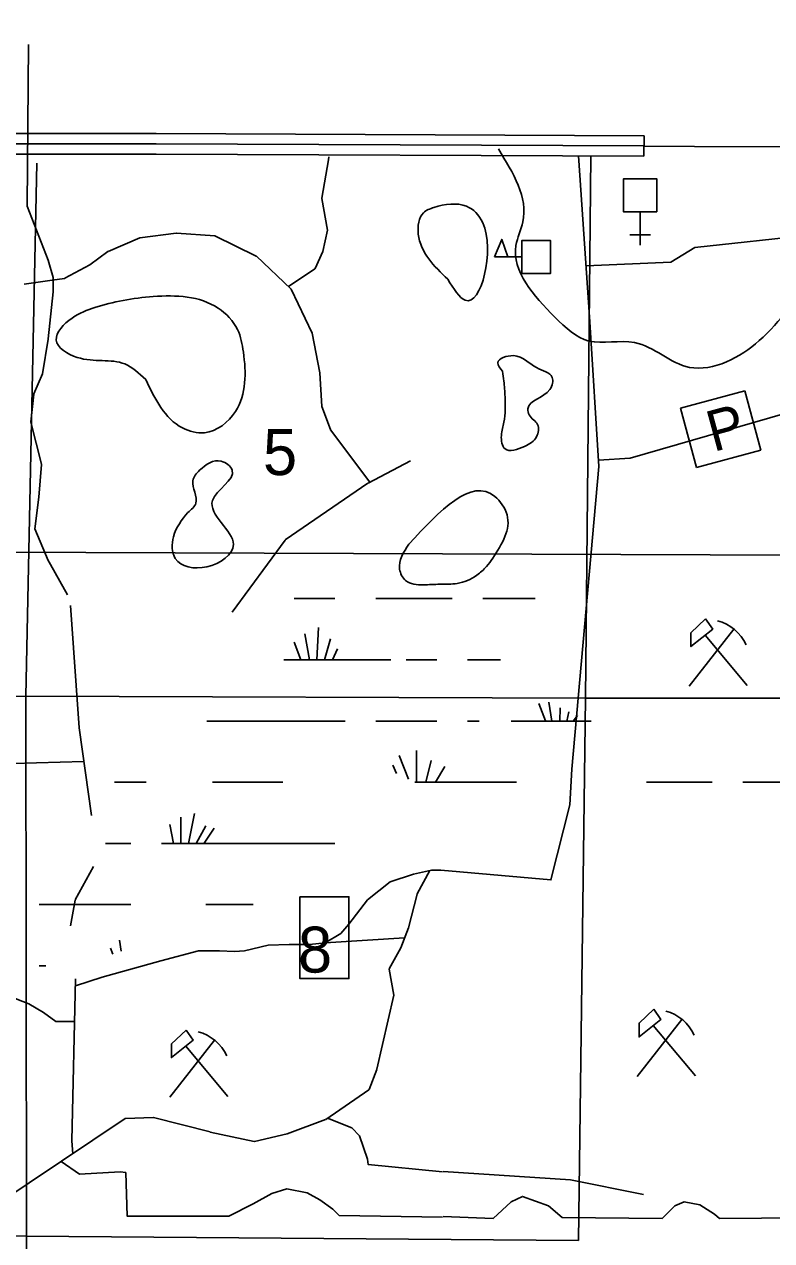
# Model space of a CAD drawing. Extents: x 408847 to 817539, y 923858 to 1151780.
# Drawn here: x 515560 to 522887, y 1099109 to 1111033 of the extents above; entities that cross this region are included whole.
import ezdxf

# ---------------------------------------------------------------- set-up
doc = ezdxf.new("R2010")
doc.units = 0
for name, color, linetype in [('County Route Divided Highway Outline and Fill', 7, 'Continuous'), ('County Routes Highway Center Lines', 7, 'Continuous'), ('Culture', 7, 'Continuous'), ('Lakes and Ponds', 7, 'Continuous'), ('Level 43', 7, 'Continuous'), ('Level 8', 7, 'Continuous'), ('Local Roads Paved', 7, 'Continuous'), ('Local Roads Related Cells', 7, 'Continuous'), ('Local Roads Related Text', 7, 'Continuous'), ('Masks for Text', 7, 'Continuous'), ('Narrow River Creek and Branch and Slough', 7, 'Continuous'), ('Quad Borders', 7, 'Continuous'), ('Section Lines', 7, 'Continuous'), ('Swamps', 7, 'Continuous')]:
    doc.layers.add(name, color=color, linetype=linetype)

msp = doc.modelspace()

# ---------------------------------------------------------------- linework, layer by layer
at = {"layer": 'County Route Divided Highway Outline and Fill'}
msp.add_lwpolyline([(483770, 1110858), (485025, 1110791), (485695, 1110804), (487095, 1110924), (487695, 1110924), (492040, 1110851), (493388, 1110671), (493666, 1110671), (497184, 1110665), (504437, 1110658), (507039, 1110658), (507716, 1110731), (508655, 1110731), (512766, 1110664), (514564, 1109861), (516852, 1109861), (521636, 1109841)], dxfattribs=at)
at = {"layer": 'County Routes Highway Center Lines'}
msp.add_lwpolyline([(526987, 1109832), (522131, 1109834), (521639, 1109839)], dxfattribs=at)
at = {"layer": 'Culture'}
for p, q in [((521599, 1109194), (521599, 1108868)), ((521699, 1108969), (521498, 1108969)), ((520438, 1108752), (520302, 1108752)), ((522078, 1104543), (522515, 1105103)), ((522234, 1105044), (522647, 1104551)), ((521570, 1100717), (522007, 1101276)), ((521727, 1101218), (522140, 1100725)), ((516985, 1100514), (517423, 1101073)), ((517142, 1101015), (517555, 1100522))]:
    msp.add_line(p, q, dxfattribs=at)
for points in [[(521761, 1109194), (521436, 1109194), (521436, 1109519), (521761, 1109519)], [(520170, 1108752), (520241, 1108924), (520302, 1108752)], [(520438, 1108589), (520438, 1108914), (520718, 1108914), (520718, 1108589)], [(522240, 1105204), (522310, 1105104), (522095, 1104932), (522095, 1105067)], [(521733, 1101377), (521802, 1101278), (521587, 1101106), (521587, 1101241)], [(517148, 1101174), (517217, 1101075), (517002, 1100903), (517002, 1101038)]]:
    msp.add_lwpolyline(points, close=True, dxfattribs=at)
for centre in [(522244, 1104770), (521736, 1100944), (517152, 1100741)]:
    msp.add_arc(centre, 431, 24.5415, 74.8304, dxfattribs=at)
at = {"layer": 'Lakes and Ponds'}
msp.add_line((520154, 1105798), (520154, 1105798), dxfattribs=at)
for points in [[(519711, 1108534), (519882, 1108327), (520054, 1109088), (519895, 1109249), (519576, 1109237), (519474, 1109186), (519423, 1108977), (519711, 1108534)], [(516750, 1107550), (517111, 1107076), (517327, 1107029), (517630, 1107237), (517708, 1107819), (517650, 1108040), (517460, 1108251), (516824, 1108364), (516251, 1108256), (516028, 1108153), (515873, 1107937), (516078, 1107768), (516544, 1107703), (516750, 1107550)], [(520249, 1107631), (520261, 1107536), (520273, 1107382), (520261, 1107133), (520237, 1107002), (520273, 1106871), (520463, 1106895), (520582, 1106990), (520593, 1107109), (520510, 1107204), (520498, 1107263), (520712, 1107453), (520736, 1107572), (520582, 1107667), (520356, 1107785), (520202, 1107714), (520249, 1107631)], [(517163, 1106248), (517022, 1106010), (517040, 1105797), (517350, 1105715), (517610, 1105932), (517404, 1106365), (517598, 1106663), (517490, 1106751), (517279, 1106661), (517212, 1106558), (517242, 1106337), (517163, 1106248)], [(519330, 1105938), (520174, 1106404), (520293, 1106224), (520154, 1105798)], [(520154, 1105798), (520090, 1105718), (519996, 1105632), (519804, 1105552), (519636, 1105544), (519470, 1105538), (519298, 1105580), (519240, 1105692), (519330, 1105938)]]:
    msp.add_spline(points, degree=3, dxfattribs=at)
at = {"layer": 'Level 8'}
msp.add_line((521636, 1109941), (521635, 1109741), dxfattribs=at)
for points in [[(482448, 1111033), (485026, 1110891), (485690, 1110904), (487091, 1111024), (487696, 1111024), (492048, 1110951), (493394, 1110771), (493666, 1110771), (497184, 1110765), (504437, 1110758), (507034, 1110758), (507711, 1110831), (508655, 1110831), (512788, 1110764), (514586, 1109961), (516852, 1109961), (521636, 1109941)], [(521635, 1109741), (516851, 1109761), (514543, 1109761), (512744, 1110565), (508654, 1110631), (507721, 1110631), (507044, 1110558), (504437, 1110558), (497184, 1110565), (493666, 1110571), (493381, 1110571), (492033, 1110751), (487695, 1110824), (487100, 1110824), (485700, 1110705), (485023, 1110691), (482448, 1110831)]]:
    msp.add_lwpolyline(points, dxfattribs=at)
at = {"layer": 'Local Roads Paved'}
for p, q in [((515587, 1109252), (515602, 1110836)), ((518543, 1109704), (518477, 1109327)), ((518545, 1109735), (518543, 1109705)), ((518477, 1109326), (518533, 1109016)), ((515795, 1108722), (515588, 1109250)), ((516692, 1108939), (516381, 1108807)), ((517050, 1108986), (516693, 1108939)), ((517428, 1108958), (517051, 1108986)), ((517834, 1108760), (517429, 1108958)), ((518533, 1109014), (518486, 1108807)), ((516380, 1108807), (516201, 1108675)), ((518486, 1108807), (518411, 1108638)), ((515842, 1108552), (515795, 1108722)), ((518174, 1108439), (517835, 1108759)), ((516201, 1108675), (515956, 1108543)), ((518409, 1108636), (518151, 1108461)), ((515833, 1108524), (515560, 1108486)), ((515955, 1108542), (515833, 1108524)), ((515842, 1108410), (515842, 1108551)), ((518382, 1108005), (518175, 1108438)), ((515795, 1107948), (515842, 1108410)), ((518458, 1107617), (518382, 1108004)), ((515739, 1107608), (515795, 1107947)), ((515654, 1107410), (515738, 1107607)), ((518476, 1107287), (518458, 1107617)), ((515625, 1107136), (515654, 1107408)), ((518561, 1107060), (518477, 1107286)), ((515729, 1106720), (515625, 1107134)), ((518948, 1106544), (518562, 1107059)), ((515701, 1106398), (515729, 1106719)), ((518930, 1106535), (519345, 1106752)), ((518118, 1105978), (518929, 1106534)), ((515663, 1106088), (515701, 1106398)), ((515795, 1105775), (515663, 1106086)), ((517598, 1105269), (518117, 1105977)), ((515786, 1105788), (515984, 1105439)), ((516012, 1105335), (516097, 1104135)), ((516097, 1104135), (516220, 1103276)), ((516145, 1103805), (515446, 1103786)), ((516239, 1102778), (516060, 1102449)), ((519411, 1102508), (519537, 1102738)), ((519326, 1102177), (519411, 1102507)), ((516059, 1102448), (516012, 1102194)), ((519251, 1101979), (519326, 1102177)), ((518510, 1102028), (519288, 1102078)), ((519138, 1101772), (519250, 1101978)), ((519184, 1101517), (519138, 1101769)), ((519015, 1100789), (519184, 1101515)), ((518940, 1100591), (519015, 1100788)), ((518515, 1100298), (518938, 1100589)), ((515211, 1099410), (516550, 1100306)), ((516552, 1100307), (516824, 1100316)), ((516825, 1100316), (517381, 1100175)), ((518137, 1100156), (518514, 1100297)), ((517381, 1100174), (517815, 1100080)), ((517816, 1100080), (518136, 1100156))]:
    msp.add_line(p, q, dxfattribs=at)
for points in [[(519645, 1102742), (520723, 1102645), (520907, 1103382), (520928, 1103730), (521194, 1106697), (521106, 1108115), (520994, 1109745)], [(524512, 1109031), (523771, 1108825), (523668, 1108825), (523280, 1108968), (522134, 1108845), (521900, 1108700), (521068, 1108664)], [(524517, 1106780), (524118, 1106718), (524036, 1107209), (523480, 1107350), (521500, 1106779), (521190, 1106761)], [(516062, 1101608), (516324, 1101691), (516899, 1101852), (517267, 1101951), (517474, 1101951), (517620, 1101944), (517720, 1101951), (517950, 1102005), (518157, 1102013), (518356, 1102013), (518510, 1102028), (518663, 1102120), (518740, 1102212), (518924, 1102450), (519146, 1102627), (519376, 1102703), (519553, 1102742), (519645, 1102742)], [(516063, 1101675), (516025, 1100087), (516035, 1099961)], [(516053, 1101258), (515869, 1101258), (515749, 1101345), (515603, 1101430), (515411, 1101506), (515212, 1101506), (515051, 1101499), (514844, 1101430), (514644, 1101414), (514437, 1101445), (514338, 1101491), (514223, 1101491), (513946, 1101529), (513762, 1101568), (513617, 1101583), (513486, 1101529), (513371, 1101506), (513157, 1101529), (513103, 1101560)], [(518531, 1100309), (518771, 1100215), (518847, 1100138), (518924, 1099908), (518932, 1099854), (519660, 1099785)], [(515921, 1099885), (516102, 1099762), (516500, 1099785), (516554, 1099777), (516569, 1099348), (517566, 1099348), (517804, 1099471), (517988, 1099570), (518134, 1099616), (518333, 1099578), (518456, 1099509), (518586, 1099417), (518648, 1099355), (519660, 1099340)], [(519667, 1099787), (520914, 1099705), (521630, 1099562)], [(519667, 1099347), (520158, 1099327), (520332, 1099490), (520444, 1099542), (520700, 1099450), (520833, 1099337), (521814, 1099327), (521937, 1099450), (522029, 1099490), (522182, 1099460), (522326, 1099368), (522377, 1099327), (523614, 1099337), (523860, 1099593), (524003, 1099675), (524146, 1099675), (524309, 1099531), (524442, 1099337), (525629, 1099306), (525925, 1099163), (527203, 1099153), (527173, 1099460)]]:
    msp.add_lwpolyline(points, dxfattribs=at)
for centre, start, end in [((518539, 1109705), 350.0787, 355.2425), ((518481, 1109327), 170.0786, 190.2998), ((515591, 1109252), 179.4701, 201.4379), ((516693, 1108935), 97.4996, 112.9991), ((517051, 1108982), 85.7087, 97.4996), ((517427, 1108954), 63.959, 85.7087), ((518529, 1109015), 347.202, 10.2998), ((516383, 1108803), 112.9991, 126.3981), ((518482, 1108808), 336.0482, 347.202), ((515791, 1108721), 15.5167, 21.4379), ((517832, 1108756), 46.6222, 63.959), ((516199, 1108678), 298.3128, 306.3981), ((518407, 1108640), 304.1731, 336.0482), ((515832, 1108528), 277.8572, 278.7505), ((515838, 1108551), 0, 15.5167), ((515954, 1108546), 278.7505, 298.3128), ((518171, 1108436), 25.5487, 46.6222), ((515838, 1108410), 354.1766, 0), ((518378, 1108003), 11.0355, 25.5487), ((515791, 1107948), 350.5424, 354.1766), ((515735, 1107608), 336.8118, 350.5424), ((518454, 1107616), 3.2688, 11.0355), ((515657, 1107408), 156.8118, 174.0968), ((518480, 1107287), 183.2688, 200.5466), ((515629, 1107135), 174.0968, 194.0295), ((518565, 1107061), 200.5466, 216.8561), ((515725, 1106719), 354.9601, 14.0295), ((518932, 1106531), 117.6091, 124.4654), ((515697, 1106399), 353.0922, 354.9601), ((515667, 1106087), 173.0922, 202.9784), ((518121, 1105974), 124.4654, 143.7599), ((519415, 1102506), 151.4017, 165.5862), ((519322, 1102178), 339.1551, 345.5862), ((519247, 1101980), 331.4017, 339.1551), ((519142, 1101770), 151.4017, 190.4863), ((519180, 1101516), 346.8488, 10.4863), ((519011, 1100790), 339.1551, 346.8488), ((518936, 1100593), 304.576, 339.1551), ((516552, 1100303), 91.9759, 123.7964), ((516824, 1100312), 75.7286, 91.9759), ((518512, 1100301), 290.5655, 304.576), ((517382, 1100178), 255.7286, 257.7292), ((518135, 1100159), 283.2469, 290.5655), ((517816, 1100084), 257.7292, 283.2469)]:
    msp.add_arc(centre, 4, start, end, dxfattribs=at)
at = {"layer": 'Local Roads Related Cells'}
for p, q in [((522623, 1107441), (521992, 1107269)), ((522781, 1106859), (522623, 1107441)), ((521992, 1107269), (522151, 1106687)), ((522151, 1106687), (522781, 1106859))]:
    msp.add_line(p, q, dxfattribs=at)
at = {"layer": 'Masks for Text'}
msp.add_lwpolyline([(518262, 1102480), (518743, 1102480), (518743, 1101678), (518262, 1101678)], close=True, dxfattribs=at)
at = {"layer": 'Narrow River Creek and Branch and Slough'}
msp.add_spline([(520208, 1109811), (520447, 1109095), (520380, 1108865), (520762, 1108163), (521096, 1107928), (521543, 1107913), (522081, 1107670), (522443, 1107723), (522765, 1107932), (523821, 1109260), (524231, 1109522), (524833, 1109464), (525534, 1109023), (525980, 1109291), (526449, 1109315), (526813, 1109622), (527284, 1109842), (527391, 1109896), (527615, 1110057)], degree=3, dxfattribs=at)
at = {"layer": 'Quad Borders'}
msp.add_line((493959, 1105933), (534527, 1105790), dxfattribs=at)
at = {"layer": 'Section Lines'}
for p, q in [((515575, 1104445), (515681, 1109672)), ((521062, 1104426), (521115, 1109744)), ((511016, 1104347), (515575, 1104445)), ((515582, 1099153), (515575, 1104445)), ((521062, 1104426), (515575, 1104445)), ((521062, 1104426), (520992, 1099109)), ((521062, 1104426), (526423, 1104430)), ((511028, 1099190), (515582, 1099153)), ((515575, 1093793), (515582, 1099153)), ((515582, 1099153), (520992, 1099109))]:
    msp.add_line(p, q, dxfattribs=at)
at = {"layer": 'Swamps'}
for p, q in [((519005, 1105403), (519755, 1105403)), ((520055, 1105403), (520505, 1105403)), ((518427, 1104803), (518444, 1105119)), ((518356, 1104803), (518309, 1105057)), ((518503, 1104803), (518561, 1105007)), ((518270, 1104803), (518205, 1104975)), ((518580, 1104803), (518629, 1104911)), ((518105, 1104803), (519155, 1104803)), ((519305, 1104803), (519605, 1104803)), ((520671, 1104204), (520605, 1104376)), ((519005, 1104203), (519605, 1104203)), ((519404, 1103914), (519404, 1103603)), ((519549, 1103817), (519495, 1103603)), ((519682, 1103757), (519592, 1103603)), ((522605, 1103603), (523055, 1103603)), ((517096, 1103261), (517096, 1103003)), ((517229, 1103297), (517170, 1103003)), ((516987, 1103189), (517024, 1103003)), ((517338, 1103177), (517244, 1103002)), ((517422, 1103152), (517323, 1103004)), ((516905, 1103003), (518605, 1103003)), ((515705, 1102403), (516305, 1102403)), ((516305, 1102403), (516605, 1102403))]:
    msp.add_line(p, q, dxfattribs=at)
for points in [[(518205, 1105403), (518605, 1105403)], [(520505, 1105403), (520568, 1105403)], [(519905, 1104803), (520228, 1104803)], [(520733, 1104203), (520704, 1104387)], [(520811, 1104203), (520814, 1104332)], [(520878, 1104202), (520897, 1104293)], [(517348, 1104203), (518705, 1104203)], [(519905, 1104203), (520019, 1104203)], [(520334, 1104203), (520505, 1104203)], [(520505, 1104203), (521118, 1104203)], [(520940, 1104202), (520982, 1104258)], [(519235, 1103865), (519326, 1103633)], [(519174, 1103769), (519209, 1103688)], [(516443, 1103603), (516755, 1103603)], [(517404, 1103603), (518096, 1103603)], [(519390, 1103603), (520385, 1103603)], [(521659, 1103603), (522305, 1103603)], [(516355, 1103003), (516605, 1103003)], [(517339, 1102403), (517805, 1102403)], [(516511, 1101947), (516494, 1102056)], [(516428, 1101916), (516405, 1101976)], [(515705, 1101803), (515770, 1101803)]]:
    msp.add_lwpolyline(points, dxfattribs=at)

# ---------------------------------------------------------------- texts
at = {"layer": 'Level 43'}
for s, p in [('5', (517900, 1106614)), ('8', (518243, 1101737))]:
    msp.add_text(s, height=450, rotation=360, dxfattribs=at).set_placement(p)
at = {"layer": 'Local Roads Related Text'}
msp.add_text('P', height=400, rotation=15.2639, dxfattribs=at).set_placement((522316, 1106839))

doc.saveas('drawing.dxf')
